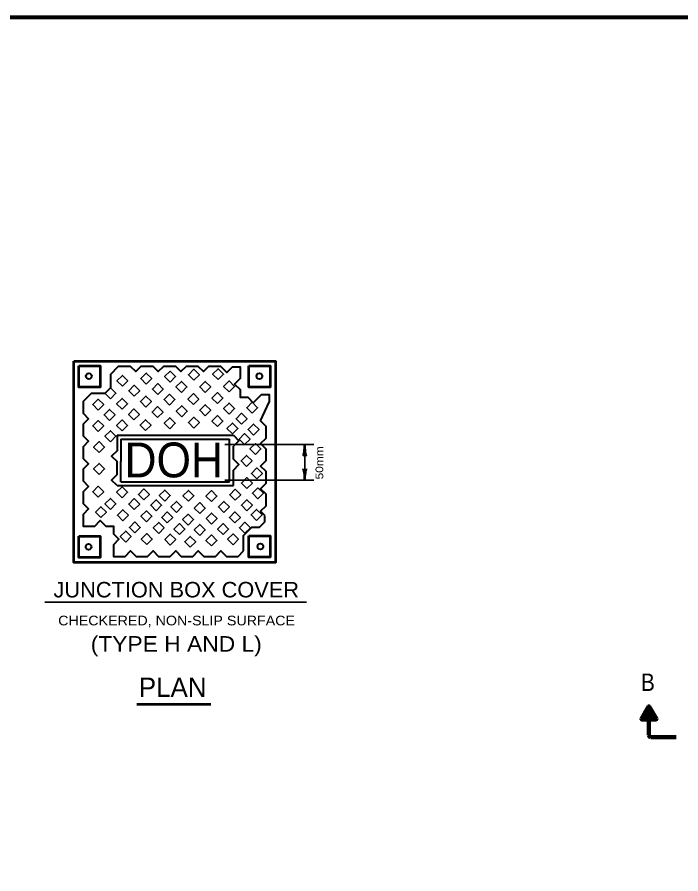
# Model space of a CAD drawing. Extents: x 442 to 1297, y -1132 to -588.
# Drawn here: x 835.5 to 1041, y -859.6 to -594.1 of the extents above; entities that cross this region are included whole.
import ezdxf
from ezdxf.enums import TextEntityAlignment as Align

# ---------------------------------------------------------------- set-up
doc = ezdxf.new("R2010")
doc.units = 0
doc.header["$LTSCALE"] = 0.96
doc.layers.add('1', color=7, linetype='Continuous', lineweight=35)

msp = doc.modelspace()

# ---------------------------------------------------------------- linework, layer by layer
at = {"layer": '1', "lineweight": 40}
for p, q in [((864.3463, -704.7711), (864.3463, -708.9711)), ((862.6492, -710.6682), (864.3463, -708.9711)), ((910.863, -719.2138), (913.5541, -713.4197)), ((866.4334, -723.6262), (902.4334, -723.6262)), ((867.6334, -724.8262), (901.2334, -724.8262)), ((867.6334, -724.8262), (867.6334, -731.8204)), ((901.2334, -734.4262), (901.2334, -724.8262)), ((867.6334, -738.0262), (867.6334, -731.8204)), ((901.2334, -738.0262), (901.2334, -734.4262)), ((867.6334, -738.0262), (901.2334, -738.0262)), ((866.4334, -739.2262), (902.4334, -739.2262)), ((903.8688, -761.179), (905.5659, -759.4819))]:
    msp.add_line(p, q, dxfattribs=at)
at = {"layer": '1'}
for p, q in [((899.7752, -726.523), (927.3752, -726.523)), ((924.5077, -737.5378), (924.5077, -726.523)), ((899.7752, -737.5378), (927.3752, -737.5378)), ((844.041, -775.3868), (925.1096, -775.3868))]:
    msp.add_line(p, q, dxfattribs=at)
at = {"layer": '1', "lineweight": 53}
msp.add_line((872.5232, -806.9628), (895.4895, -806.9628), dxfattribs=at)
at = {"layer": '1', "lineweight": 140}
for p, q in [((1030.982, -807.7333), (1028.7898, -811.5301)), ((1029.841, -809.7095), (1032.3308, -809.7095)), ((1029.9039, -809.6006), (1032.2679, -809.6006)), ((1029.9588, -809.5054), (1032.213, -809.5054)), ((1030.053, -809.3422), (1032.1188, -809.3422)), ((1030.1238, -809.2197), (1032.048, -809.2197)), ((1030.163, -809.1517), (1032.0088, -809.1517)), ((1030.1866, -809.1109), (1031.9852, -809.1109)), ((1030.2338, -809.0292), (1031.938, -809.0292)), ((1030.2966, -808.9204), (1031.8752, -808.9204)), ((1030.3594, -808.8116), (1031.8124, -808.8116)), ((1030.3987, -808.7436), (1031.7731, -808.7436)), ((1030.4537, -808.6483), (1031.7181, -808.6483)), ((1030.4929, -808.5803), (1031.6789, -808.5803)), ((1030.5244, -808.5259), (1031.6474, -808.5259)), ((1030.5558, -808.4715), (1031.616, -808.4715)), ((1030.5951, -808.4034), (1031.5767, -808.4034)), ((1030.6579, -808.2946), (1031.5139, -808.2946)), ((1030.7285, -808.1722), (1031.4432, -808.1722)), ((1030.76, -808.1177), (1031.4118, -808.1177)), ((1030.8071, -808.0361), (1031.3647, -808.0361)), ((1030.9092, -807.8593), (1031.2626, -807.8593)), ((1031.0035, -807.696), (1031.1683, -807.696)), ((1031.0859, -816.5804), (1031.0859, -807.5804)), ((1031.1898, -807.7333), (1033.382, -811.5301)), ((1028.7492, -811.6005), (1033.4226, -811.6005)), ((1028.8041, -811.5053), (1033.3677, -811.5053)), ((1028.8592, -811.41), (1033.3126, -811.41)), ((1028.8906, -811.3556), (1033.2812, -811.3556)), ((1028.8937, -811.7101), (1033.2781, -811.7101)), ((1028.9534, -811.2468), (1033.2184, -811.2468)), ((1029.0163, -811.1379), (1033.1555, -811.1379)), ((1029.1026, -810.9883), (1033.0692, -810.9883)), ((1029.1733, -810.8659), (1032.9985, -810.8659)), ((1029.244, -810.7434), (1032.9278, -810.7434)), ((1029.2833, -810.6754), (1032.8885, -810.6754)), ((1029.3461, -810.5666), (1032.8257, -810.5666)), ((1029.3933, -810.4849), (1032.7785, -810.4849)), ((1029.4875, -810.3217), (1032.6843, -810.3217)), ((1029.5504, -810.2128), (1032.6214, -810.2128)), ((1029.5975, -810.1312), (1032.5743, -810.1312)), ((1029.6525, -810.036), (1032.5193, -810.036)), ((1029.6917, -809.968), (1032.4801, -809.968)), ((1029.7546, -809.8591), (1032.4172, -809.8591)), ((1039.4859, -817.1804), (1031.6859, -817.1804))]:
    msp.add_line(p, q, dxfattribs=at)
at = {"layer": '1', "lineweight": 158}
msp.add_lwpolyline([(1290.7447, -594.0679), (499.0447, -594.1679), (499.1447, -1120.1679)], dxfattribs=at)
at = {"layer": '1', "lineweight": 53}
for points in [[(853.0771, -700.6629), (915.4771, -700.6629), (915.4771, -763.0629), (853.0771, -763.0629)], [(854.5851, -702.1204), (861.1851, -702.1204), (861.1851, -708.7204), (854.5851, -708.7204)], [(907.2666, -702.1205), (913.8666, -702.1205), (913.8666, -708.7205), (907.2666, -708.7205)], [(854.585, -754.9026), (861.185, -754.9026), (861.185, -761.5026), (854.585, -761.5026)], [(907.2668, -754.8021), (913.8668, -754.8021), (913.8668, -761.4021), (907.2668, -761.4021)]]:
    msp.add_lwpolyline(points, close=True, dxfattribs=at)
at = {"layer": '1', "lineweight": 40}
for points in [[(864.3463, -704.7711), (866.8919, -702.2255), (870.4919, -702.2255), (872.189, -703.9226), (873.8861, -702.2255), (877.4861, -702.2255), (879.1832, -703.9226), (880.8803, -702.2255), (884.4803, -702.2255), (886.1774, -703.9226), (887.8745, -702.2255), (891.4745, -702.2255), (893.1716, -703.9226), (894.8687, -702.2255), (898.4687, -702.2255), (900.4143, -704.1711), (902.1114, -702.474), (904.5114, -702.474), (904.5114, -706.074), (902.8143, -707.7711), (904.5114, -709.4682), (904.5114, -711.8682), (906.9114, -711.8682), (908.6085, -713.5653), (911.1541, -711.0197), (913.5541, -711.0197), (913.5541, -713.4197)], [(862.6492, -710.6682), (858.4492, -710.6682), (855.9036, -713.2138), (855.9036, -716.8138), (857.6007, -718.5109), (855.9036, -720.208), (855.9036, -723.808), (857.6007, -725.5051), (855.9036, -727.2022), (855.9036, -730.8022), (857.6007, -732.4993), (855.9036, -734.1964), (855.9036, -737.7964), (857.6007, -739.4935), (855.9036, -741.1906), (855.9036, -744.7906), (857.6007, -746.4877), (855.9036, -748.1848), (855.9036, -751.7848), (859.5036, -751.7848), (861.2007, -750.0877), (862.8978, -751.7848), (865.2978, -751.7848), (865.2978, -754.1848), (866.9949, -755.8819), (865.2978, -757.579), (865.2978, -761.179), (868.8978, -761.179), (870.5949, -759.4819), (872.292, -761.179), (875.892, -761.179), (877.5891, -759.4819), (879.2862, -761.179), (882.8862, -761.179), (884.5833, -759.4819), (886.2804, -761.179), (889.8804, -761.179), (891.5775, -759.4819), (893.2746, -761.179), (896.8746, -761.179)], [(912.2086, -748.5362), (910.863, -747.1906), (912.5601, -745.4935), (912.5601, -741.8935), (910.863, -740.1964), (912.5601, -738.4993), (912.5601, -734.8993), (910.863, -733.2022), (912.5601, -731.5051), (912.5601, -727.9051), (910.863, -726.208), (912.5601, -724.5109), (912.5601, -720.9109), (910.863, -719.2138)], [(866.4334, -723.6262), (866.4334, -728.4262), (864.7363, -730.1233), (866.4334, -731.8204)], [(902.4334, -723.6262), (904.1305, -725.3233), (902.4334, -727.0204)], [(902.4334, -739.2262), (902.4334, -734.4262), (904.1305, -732.7291), (902.4334, -731.032), (902.4334, -727.0204)], [(866.4334, -739.2262), (864.7363, -737.5291), (866.4334, -735.832), (866.4334, -731.8204)], [(905.5659, -759.4819), (905.5659, -754.6819), (908.1115, -752.1363), (910.5115, -752.1363), (912.2086, -750.4392), (912.2086, -748.5362)], [(896.8746, -761.179), (898.5717, -759.4819), (900.2688, -761.179), (903.8688, -761.179)]]:
    msp.add_lwpolyline(points, dxfattribs=at)
at = {"layer": '1'}
for points in [[(890.2096, -706.5768), (891.9067, -704.8797), (890.2096, -703.1826), (888.5125, -704.8797)], [(897.6808, -706.405), (899.3779, -704.7079), (897.6808, -703.0108), (895.9837, -704.7079)], [(868.0537, -708.4661), (869.7508, -706.769), (868.0537, -705.0719), (866.3566, -706.769)], [(875.439, -707.779), (877.1361, -706.0819), (875.439, -704.3848), (873.7419, -706.0819)], [(882.8243, -707.1779), (884.5214, -705.4808), (882.8243, -703.7837), (881.1272, -705.4808)], [(871.7464, -711.5576), (873.4435, -709.8605), (871.7464, -708.1634), (870.0493, -709.8605)], [(879.0458, -711.0423), (880.7429, -709.3452), (879.0458, -707.6481), (877.3487, -709.3452)], [(886.3452, -710.3553), (888.0423, -708.6582), (886.3452, -706.9611), (884.6481, -708.6582)], [(893.7305, -710.3553), (895.4276, -708.6582), (893.7305, -706.9611), (892.0334, -708.6582)], [(901.1158, -710.1836), (902.8129, -708.4865), (901.1158, -706.7894), (899.4187, -708.4865)], [(864.361, -712.3305), (866.0581, -710.6334), (864.361, -708.9363), (862.6639, -710.6334)], [(882.6527, -714.3056), (884.3498, -712.6085), (882.6527, -710.9114), (880.9556, -712.6085)], [(890.0379, -714.1339), (891.735, -712.4368), (890.0379, -710.7397), (888.3408, -712.4368)], [(897.5091, -713.7904), (899.2062, -712.0933), (897.5091, -710.3962), (895.812, -712.0933)], [(860.5824, -715.8515), (862.2795, -714.1544), (860.5824, -712.4573), (858.8853, -714.1544)], [(867.9678, -715.5938), (869.6649, -713.8967), (867.9678, -712.1996), (866.2707, -713.8967)], [(875.3532, -714.9068), (877.0503, -713.2097), (875.3532, -711.5126), (873.6561, -713.2097)], [(901.1159, -717.0537), (902.813, -715.3566), (901.1159, -713.6595), (899.4188, -715.3566)], [(908.2436, -716.7961), (909.9407, -715.099), (908.2436, -713.4019), (906.5465, -715.099)], [(864.1034, -719.0289), (865.8005, -717.3318), (864.1034, -715.6347), (862.4063, -717.3318)], [(871.6605, -718.8571), (873.3576, -717.16), (871.6605, -715.4629), (869.9634, -717.16)], [(878.96, -718.1701), (880.6571, -716.473), (878.96, -714.7759), (877.2629, -716.473)], [(886.4312, -717.9124), (888.1283, -716.2153), (886.4312, -714.5182), (884.7341, -716.2153)], [(893.7306, -717.5689), (895.4277, -715.8718), (893.7306, -714.1747), (892.0335, -715.8718)], [(860.5825, -722.4639), (862.2796, -720.7668), (860.5825, -719.0697), (858.8854, -720.7668)], [(867.9678, -722.2922), (869.6649, -720.5951), (867.9678, -718.898), (866.2707, -720.5951)], [(875.2673, -722.2063), (876.9644, -720.5092), (875.2673, -718.8121), (873.5702, -720.5092)], [(882.7386, -721.6052), (884.4357, -719.9081), (882.7386, -718.211), (881.0415, -719.9081)], [(890.2098, -721.4334), (891.9069, -719.7363), (890.2098, -718.0392), (888.5127, -719.7363)], [(897.5092, -720.9181), (899.2063, -719.221), (897.5092, -717.5239), (895.8121, -719.221)], [(904.9803, -720.2311), (906.6774, -718.534), (904.9803, -716.8369), (903.2832, -718.534)], [(902.1464, -723.2368), (903.8435, -721.5397), (902.1464, -719.8426), (900.4493, -721.5397)], [(908.673, -723.5803), (910.3701, -721.8832), (908.673, -720.1861), (906.9759, -721.8832)], [(864.3611, -725.6413), (866.0582, -723.9442), (864.3611, -722.2471), (862.664, -723.9442)], [(905.9251, -726.5001), (907.6222, -724.803), (905.9251, -723.1059), (904.228, -724.803)], [(860.8402, -728.9905), (862.5373, -727.2934), (860.8402, -725.5963), (859.1431, -727.2934)], [(909.2744, -729.5916), (910.9715, -727.8945), (909.2744, -726.1974), (907.5773, -727.8945)], [(906.5262, -733.2843), (908.2233, -731.5872), (906.5262, -729.8901), (904.8291, -731.5872)], [(860.8402, -735.7748), (862.5373, -734.0777), (860.8402, -732.3806), (859.1431, -734.0777)], [(909.7037, -737.1487), (911.4008, -735.4516), (909.7037, -733.7545), (908.0066, -735.4516)], [(906.6122, -740.1544), (908.3093, -738.4573), (906.6122, -736.7602), (904.9151, -738.4573)], [(860.5825, -742.8167), (862.2796, -741.1196), (860.5825, -739.4225), (858.8854, -741.1196)], [(867.9679, -742.9884), (869.665, -741.2913), (867.9679, -739.5942), (866.2708, -741.2913)], [(874.7521, -743.6753), (876.4492, -741.9782), (874.7521, -740.2811), (873.055, -741.9782)], [(881.1928, -744.0188), (882.8899, -742.3217), (881.1928, -740.6246), (879.4957, -742.3217)], [(888.4922, -744.1048), (890.1893, -742.4077), (888.4922, -740.7106), (886.7951, -742.4077)], [(903.0054, -743.7612), (904.7025, -742.0641), (903.0054, -740.367), (901.3083, -742.0641)], [(910.0473, -743.3318), (911.7444, -741.6347), (910.0473, -739.9376), (908.3502, -741.6347)], [(864.3611, -746.5952), (866.0582, -744.8981), (864.3611, -743.201), (862.664, -744.8981)], [(871.7465, -746.6811), (873.4436, -744.984), (871.7465, -743.2869), (870.0494, -744.984)], [(895.62, -744.1906), (897.3171, -742.4935), (895.62, -740.7964), (893.9229, -742.4935)], [(861.4413, -749.1715), (863.1384, -747.4744), (861.4413, -745.7773), (859.7442, -747.4744)], [(878.5306, -747.0244), (880.2277, -745.3273), (878.5306, -743.6302), (876.8335, -745.3273)], [(884.7996, -747.5398), (886.4967, -745.8427), (884.7996, -744.1456), (883.1025, -745.8427)], [(892.0132, -747.8833), (893.7103, -746.1862), (892.0132, -744.4891), (890.3161, -746.1862)], [(899.4844, -747.5399), (901.1815, -745.8428), (899.4844, -744.1457), (897.7873, -745.8428)], [(906.6122, -747.0245), (908.3093, -745.3274), (906.6122, -743.6303), (904.9151, -745.3274)], [(868.2255, -750.1162), (869.9226, -748.4191), (868.2255, -746.722), (866.5284, -748.4191)], [(875.525, -750.4597), (877.2221, -748.7626), (875.525, -747.0655), (873.8279, -748.7626)], [(881.9657, -750.803), (883.6628, -749.1059), (881.9657, -747.4088), (880.2686, -749.1059)], [(888.4064, -751.4901), (890.1035, -749.793), (888.4064, -748.0959), (886.7093, -749.793)], [(895.7059, -751.1466), (897.403, -749.4495), (895.7059, -747.7524), (894.0088, -749.4495)], [(902.9195, -750.8031), (904.6166, -749.106), (902.9195, -747.4089), (901.2224, -749.106)], [(909.6179, -750.0302), (911.315, -748.3331), (909.6179, -746.636), (907.9208, -748.3331)], [(871.9182, -753.8947), (873.6153, -752.1976), (871.9182, -750.5005), (870.2211, -752.1976)], [(879.3036, -754.0665), (881.0007, -752.3694), (879.3036, -750.6723), (877.6065, -752.3694)], [(885.7442, -754.4098), (887.4413, -752.7127), (885.7442, -751.0156), (884.0471, -752.7127)], [(892.0132, -754.6675), (893.7103, -752.9704), (892.0132, -751.2733), (890.3161, -752.9704)], [(899.2268, -754.4099), (900.9239, -752.7128), (899.2268, -751.0157), (897.5297, -752.7128)], [(906.011, -753.9806), (907.7081, -752.2835), (906.011, -750.5864), (904.3139, -752.2835)], [(869.0843, -756.7287), (870.7814, -755.0316), (869.0843, -753.3345), (867.3872, -755.0316)], [(875.6109, -757.5015), (877.308, -755.8044), (875.6109, -754.1073), (873.9138, -755.8044)], [(882.9104, -757.6733), (884.6075, -755.9762), (882.9104, -754.2791), (881.2133, -755.9762)], [(889.0937, -758.3604), (890.7908, -756.6633), (889.0937, -754.9662), (887.3966, -756.6633)], [(895.62, -757.9308), (897.3171, -756.2337), (895.62, -754.5366), (893.9229, -756.2337)], [(902.3183, -757.5874), (904.0154, -755.8903), (902.3183, -754.1932), (900.6212, -755.8903)]]:
    msp.add_lwpolyline(points, close=True, dxfattribs=at)
at = {"layer": '1', "lineweight": 40}
for centre in [(857.7018, -705.3377), (910.4838, -705.3378), (857.6012, -758.2204), (910.7856, -758.1199)]:
    msp.add_circle(centre, 0.9, dxfattribs=at)
at = {"layer": '1', "lineweight": 140}
for centre, radius, start, end in [((1031.0859, -807.7933), 0.12, 30.00101, 149.99899), ((1028.8937, -811.5901), 0.12, 149.99927, 270), ((1033.2781, -811.5901), 0.12, 270, 30.00073), ((1031.6859, -816.5804), 0.6, 180, 270)]:
    msp.add_arc(centre, radius, start, end, dxfattribs=at)
at = {"layer": '1', "lineweight": 40}
for centre, major_axis, ratio, start_param, end_param in [((924.2538, -727.8676), (-0.2108, -2.1077), 0.07063, 6.28230741, 8.55970261), ((924.8393, -727.8324), (-0.1874, 2.1428), 0.122415, 0.89635335, 3.14159265), ((924.1761, -736.2284), (0.1874, -2.1428), 0.122415, 0.89635335, 3.14159265), ((924.7616, -736.1932), (0.2108, 2.1077), 0.07063, 6.28230741, 8.55970261)]:
    msp.add_ellipse(centre, major_axis=major_axis, ratio=ratio, start_param=start_param, end_param=end_param, dxfattribs=at)

# ---------------------------------------------------------------- texts
at = {"layer": '1'}
for s, height, width, p in [('DOH', 10.8, 0.95, (883.9737, -736.6892)), ('JUNCTION BOX COVER', 4.8, 1.05, (884.7467, -773.8894)), ('(TYPE H AND L)', 4.8, 1.1, (884.7467, -790.6894)), ('B', 5.4, 0.9, (1030.7496, -802.8703))]:
    msp.add_text(s, height=height, dxfattribs=dict(at, width=width)).set_placement(p, align=Align.CENTER)
at = {"layer": '1', "width": 1.15}
msp.add_text('50mm', height=2.4, rotation=90, dxfattribs=at).set_placement((930.2574, -732.1965), align=Align.CENTER)
at = {"layer": '1', "width": 1.1}
msp.add_text('CHECKERED, NON-SLIP SURFACE', height=3, dxfattribs=at).set_placement((848.197, -782.5559))
at = {"layer": '1'}
msp.add_text('PLAN', height=6, dxfattribs=at).set_placement((883.6376, -804.7392), align=Align.CENTER)

doc.saveas('drawing.dxf')
